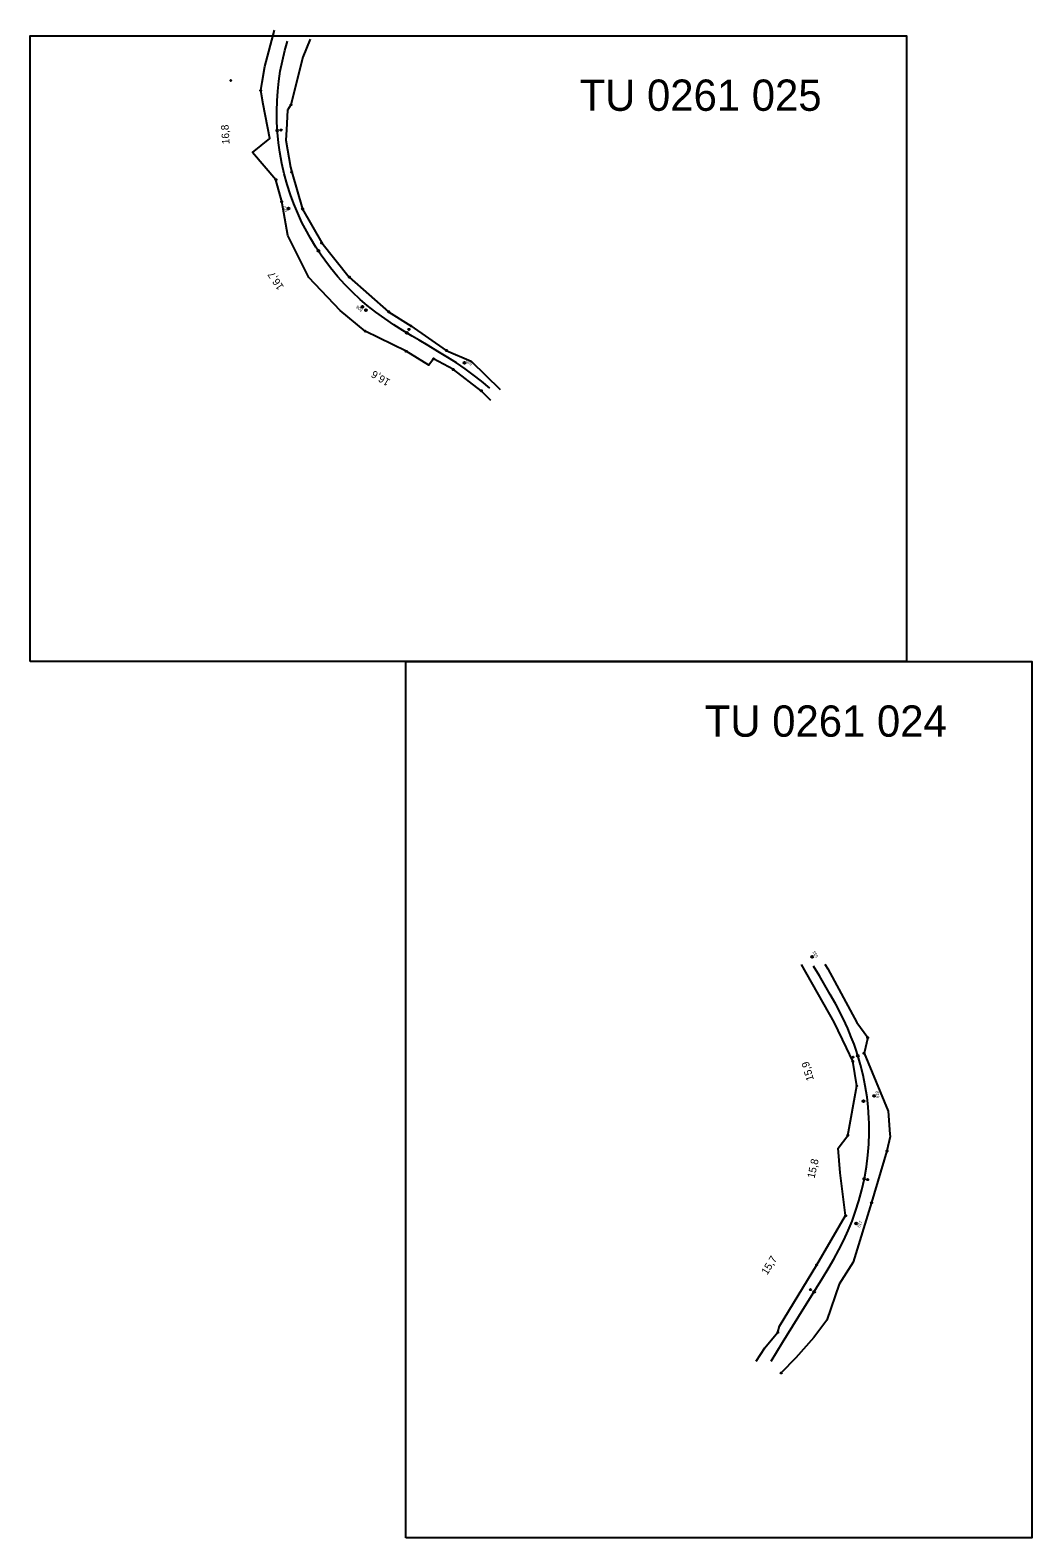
# Model space of a CAD drawing. Extents: x -849500 to -843400, y -1061500 to -1052696.
# Drawn here: x -849500 to -848700, y -1053900 to -1052696 of the extents above; entities that cross this region are included whole.
import ezdxf

# ---------------------------------------------------------------- set-up
doc = ezdxf.new("R2010")
doc.units = 0
for name, color, linetype in [('Level 1', 7, 'Continuous'), ('Level 2', 7, 'Continuous'), ('Vrstva 1', 7, 'Continuous'), ('Vrstva 53', 7, 'Continuous'), ('Vrstva 63', 7, 'Continuous'), ('Vrstva 7', 7, 'Continuous')]:
    doc.layers.add(name, color=color, linetype=linetype)

msp = doc.modelspace()

# ---------------------------------------------------------------- linework, layer by layer
at = {"layer": 'Level 1'}
for points in [[(-849500, -1053200), (-849500, -1052700), (-848800, -1052700), (-848800, -1053200), (-849500, -1053200)], [(-849200, -1053900), (-849200, -1053200), (-848700, -1053200), (-848700, -1053900), (-849200, -1053900)]]:
    msp.add_lwpolyline(points, dxfattribs=at)
at = {"layer": 'Vrstva 1'}
for points in [[(-849132.9, -1052981.5), (-849139.5, -1052975.9), (-849146.1, -1052970.8), (-849152.7, -1052966), (-849159.5, -1052961.3), (-849166.4, -1052957), (-849174.3, -1052952.2), (-849182.1, -1052947.5), (-849189.4, -1052943.3), (-849194.8, -1052940.1), (-849202.3, -1052935.5), (-849209.5, -1052930.9), (-849216.7, -1052926), (-849223.9, -1052920.9), (-849230.8, -1052915.4), (-849236.4, -1052910.6), (-849242.5, -1052904.9), (-849248.6, -1052898.7), (-849254.2, -1052892.6), (-849260.1, -1052885.4), (-849264.6, -1052879.4), (-849267.6, -1052875.3), (-849271.8, -1052869), (-849276.2, -1052861.7), (-849280.4, -1052854.1), (-849283, -1052849.1), (-849286.3, -1052841.7), (-849289.4, -1052834.2), (-849292.1, -1052827), (-849294.7, -1052818.8), (-849297.1, -1052810.3), (-849299, -1052802.1), (-849300.6, -1052792.9), (-849301.7, -1052785.5), (-849302.5, -1052777.4), (-849302.9, -1052769.1), (-849303.1, -1052760.2), (-849302.8, -1052752), (-849302.3, -1052744.2), (-849301.4, -1052736.4), (-849300.2, -1052728.2), (-849298.6, -1052720.1), (-849296.6, -1052711.7), (-849294.6, -1052704.3)], [(-848908.3, -1053758.8), (-848903.7, -1053751.4), (-848899.1, -1053743.9), (-848895.6, -1053738.3), (-848890.8, -1053730.6), (-848886, -1053722.9), (-848881.2, -1053715.3), (-848876.7, -1053708.1), (-848871.9, -1053700.3), (-848867.1, -1053692.5), (-848862.6, -1053685.1), (-848858.1, -1053677.3), (-848854.1, -1053669.9), (-848850.2, -1053662.1), (-848846.7, -1053654.5), (-848843.6, -1053647), (-848840.8, -1053639.1), (-848838.1, -1053630.9), (-848835.7, -1053622.1), (-848833.7, -1053612.9), (-848832.1, -1053603.5), (-848830.9, -1053594.3), (-848830.2, -1053585.4), (-848829.9, -1053576.6), (-848829.9, -1053569), (-848830.1, -1053564.6), (-848830.7, -1053555.8), (-848831.6, -1053547.9), (-848833, -1053539), (-848834.7, -1053530.5), (-848836.8, -1053522.2), (-848839, -1053514.7), (-848840.6, -1053509.6), (-848842, -1053505.7), (-848844.2, -1053500), (-848847, -1053493.2), (-848848.9, -1053489.2), (-848852.6, -1053481.4), (-848856.6, -1053473.7), (-848861, -1053465.9), (-848865.3, -1053458.4), (-848869.7, -1053451), (-848874.3, -1053443.3)]]:
    msp.add_lwpolyline(points, dxfattribs=at)
at = {"layer": 'Vrstva 53'}
for p, q in [((-849339.8, -1052735.8), (-849339.7, -1052735.8)), ((-849315.9, -1052743.8), (-849315.8, -1052743.8)), ((-849291.7, -1052755.2), (-849291.6, -1052755.2)), ((-849291.1, -1052809), (-849291, -1052809)), ((-849303.8, -1052815), (-849303.7, -1052815)), ((-849299.1, -1052832.5), (-849299, -1052832.5)), ((-849282.4, -1052838.5), (-849282.3, -1052838.5)), ((-849267.1, -1052865.5), (-849267, -1052865.5)), ((-849245.2, -1052892.8), (-849245.1, -1052892.8)), ((-849213.7, -1052920.5), (-849213.6, -1052920.5)), ((-849232.4, -1052936), (-849232.3, -1052936)), ((-849196, -1052931.8), (-849195.9, -1052931.8)), ((-849199.7, -1052952.1), (-849199.6, -1052952.1)), ((-849167.7, -1052951.4), (-849167.6, -1052951.4)), ((-849177.8, -1052958.2), (-849177.7, -1052958.2)), ((-849162.1, -1052966.7), (-849162, -1052966.7)), ((-849139.7, -1052983.6), (-849139.6, -1052983.6)), ((-848831.2, -1053500.4), (-848831.1, -1053500.4)), ((-848843.1, -1053519.3), (-848843, -1053519.3)), ((-848834.1, -1053512.9), (-848834, -1053512.9)), ((-848839.9, -1053538.9), (-848839.8, -1053538.9)), ((-848847, -1053578.5), (-848846.9, -1053578.5)), ((-848815.8, -1053590.9), (-848815.7, -1053590.9)), ((-848828, -1053632.2), (-848827.9, -1053632.2)), ((-848848.7, -1053642.7), (-848848.6, -1053642.7)), ((-848871.8, -1053681.9), (-848871.8, -1053681.9)), ((-848903, -1053735.8), (-848902.9, -1053735.8)), ((-848900.2, -1053768.3), (-848900.1, -1053768.3))]:
    msp.add_line(p, q, dxfattribs=at)
for points in [[(-849132.1, -1052991.4), (-849139.7, -1052983.6), (-849162, -1052966.7), (-849177.8, -1052958.2), (-849181.6, -1052963.1), (-849199.6, -1052952.1), (-849232.4, -1052936), (-849252.3, -1052919.6), (-849277.4, -1052893.2), (-849294.1, -1052859.5), (-849299.1, -1052832.5), (-849303.7, -1052815), (-849322.4, -1052793.2), (-849308.7, -1052782.2), (-849313.8, -1052754.8), (-849315.9, -1052743.8), (-849314.8, -1052737.2), (-849312.6, -1052724.6), (-849304.8, -1052695.6)], [(-849276.5, -1052702.8), (-849282.3, -1052717.1), (-849291.7, -1052755.2), (-849294.5, -1052759.4), (-849295.4, -1052775.1), (-849295.9, -1052783.5), (-849292.2, -1052804.9), (-849291, -1052809.1), (-849282.4, -1052838.6), (-849267.1, -1052865.5), (-849245.1, -1052892.8), (-849213.7, -1052920.5), (-849196, -1052931.8), (-849167.7, -1052951.4), (-849147.7, -1052960), (-849124.5, -1052982.7)], [(-848920.3, -1053758.9), (-848913.2, -1053748.1), (-848902.9, -1053735.8), (-848901.4, -1053730.8), (-848871.8, -1053681.9), (-848848.7, -1053642.6), (-848853.2, -1053608.3), (-848854.7, -1053588.7), (-848847, -1053578.5), (-848839.8, -1053538.9), (-848843, -1053519.3), (-848848.1, -1053508.6), (-848857.8, -1053488.1), (-848884, -1053441.9)], [(-848865.2, -1053441.7), (-848863, -1053445.5), (-848839.7, -1053488.2), (-848831.1, -1053500.4), (-848834, -1053512.8), (-848814.7, -1053559.2), (-848813.3, -1053577.6), (-848813.1, -1053579.5), (-848815.7, -1053590.9), (-848828, -1053632.2), (-848842.7, -1053679.8), (-848854, -1053697.4), (-848863.7, -1053726.1), (-848874.1, -1053740), (-848888.6, -1053756.1), (-848900.2, -1053768.3), (-848900.2, -1053768.3)]]:
    msp.add_lwpolyline(points, dxfattribs=at)
for centre in [(-849339.7, -1052735.8), (-849315.9, -1052743.8), (-849291.7, -1052755.2), (-849291.1, -1052809), (-849303.7, -1052815), (-849299.1, -1052832.5), (-849282.4, -1052838.5), (-849267.1, -1052865.5), (-849245.1, -1052892.8), (-849213.7, -1052920.5), (-849232.4, -1052936), (-849196, -1052931.8), (-849199.6, -1052952.1), (-849167.7, -1052951.4), (-849177.8, -1052958.2), (-849162, -1052966.7), (-849139.7, -1052983.6), (-848831.1, -1053500.4), (-848843, -1053519.3), (-848834, -1053512.9), (-848839.8, -1053538.9), (-848847, -1053578.5), (-848815.7, -1053590.9), (-848828, -1053632.2), (-848848.7, -1053642.7), (-848871.8, -1053681.9), (-848902.9, -1053735.8), (-848900.2, -1053768.3)]:
    msp.add_circle(centre, 0.499, dxfattribs=at)
at = {"layer": 'Vrstva 63'}
for p, q in [((-849293.7, -1052838), (-849293.6, -1052838)), ((-849234.8, -1052916.5), (-849234.7, -1052916.5)), ((-849232.5, -1052919.3), (-849232.1, -1052918.9)), ((-849232.4, -1052919.6), (-849231.9, -1052919.1)), ((-849232.3, -1052918.7), (-849231.8, -1052919.2)), ((-849231.8, -1052919.2), (-849232.3, -1052919.8)), ((-849231.8, -1052919.2), (-849231.2, -1052918.7)), ((-849231.2, -1052919.8), (-849231.8, -1052919.2)), ((-849231.6, -1052919.4), (-849231.1, -1052918.8)), ((-849231.4, -1052919.6), (-849231, -1052919.2)), ((-849153.1, -1052961.3), (-849153, -1052961.3)), ((-848875.4, -1053435.9), (-848875.3, -1053435.9)), ((-848835.3, -1053551.3), (-848834.9, -1053550.9)), ((-848835.2, -1053551.6), (-848834.7, -1053551.1)), ((-848835.1, -1053550.7), (-848834.5, -1053551.2)), ((-848834.5, -1053551.2), (-848835.1, -1053551.8)), ((-848834.5, -1053551.2), (-848834, -1053550.7)), ((-848834, -1053551.8), (-848834.5, -1053551.2)), ((-848834.4, -1053551.4), (-848833.9, -1053550.9)), ((-848834.2, -1053551.6), (-848833.8, -1053551.2)), ((-848826, -1053547), (-848825.9, -1053547)), ((-848840.4, -1053648.8), (-848840.3, -1053648.8))]:
    msp.add_line(p, q, dxfattribs=at)
for centre, radius in [((-849293.7, -1052838), 0.756), ((-849234.7, -1052916.5), 0.756), ((-849231.8, -1052919.2), 0.764), ((-849153.1, -1052961.3), 0.756), ((-848875.4, -1053435.9), 0.756), ((-848834.5, -1053551.2), 0.764), ((-848825.9, -1053547), 0.756), ((-848840.3, -1053648.8), 0.756)]:
    msp.add_circle(centre, radius, dxfattribs=at)
for centre, start, end in [((-849231.8, -1052919.2), 134.6025, 224.9205), ((-849231.8, -1052919.2), 315.0532, 44.9468), ((-848834.5, -1053551.2), 134.6025, 224.9205), ((-848834.5, -1053551.2), 315.0532, 44.9468)]:
    msp.add_arc(centre, 0.765, start, end, dxfattribs=at)
at = {"layer": 'Vrstva 7'}
for p, q in [((-849299.6, -1052775.4), (-849299.6, -1052775.3)), ((-849197.4, -1052934.7), (-849197.5, -1052934.6)), ((-848842.8, -1053516), (-848842.8, -1053516.1)), ((-848831.1, -1053613.9), (-848831.1, -1053613.8)), ((-848876.9, -1053701.7), (-848876.8, -1053701.6))]:
    msp.add_line(p, q, dxfattribs=at)
for centre, radius in [((-849302.6, -1052775.6), 0.75), ((-849299.6, -1052775.4), 0.5), ((-849269.8, -1052871.9), 0.75), ((-849199.1, -1052937.4), 0.75), ((-849197.5, -1052934.6), 0.5), ((-848842.8, -1053516), 0.5), ((-848838.9, -1053514.9), 0.75), ((-848833.8, -1053613.2), 0.75), ((-848831.1, -1053613.8), 0.5), ((-848876.8, -1053701.7), 0.5), ((-848873.9, -1053703.5), 0.75)]:
    msp.add_circle(centre, radius, dxfattribs=at)

# ---------------------------------------------------------------- texts
at = {"layer": 'Level 2'}
for s, p in [('TU 0261 025', (-849061.2, -1052760)), ('TU 0261 024', (-848961.2, -1053260))]:
    msp.add_text(s, height=25, dxfattribs=at).set_placement(p)
at = {"layer": 'Vrstva 63'}
for s, rotation, p in [('507', 112.5145, (-849293.9, -1052840.1)), ('506', 139.417, (-849234.3, -1052918.9)), ('505', 145.8665, (-849146.6, -1052961.7)), ('633', 121.1707, (-848870.4, -1053435.6)), ('618', 96.478, (-848821.8, -1053548.5)), ('617', 69.9575, (-848837.3, -1053652.4))]:
    msp.add_text(s, height=2.4, rotation=rotation, dxfattribs=at).set_placement(p)
at = {"layer": 'Vrstva 7'}
for s, rotation, p in [('16,8', 93.3098, (-849340.7, -1052786.5)), ('16,7', 123.6859, (-849297.1, -1052900.6)), ('16,6', 148.6948, (-849211.9, -1052975.2)), ('15,9', 106.1631, (-848874, -1053534)), ('15,8', 77.454, (-848873.6, -1053613.2)), ('15,7', 58.1064, (-848911.4, -1053690.4))]:
    msp.add_text(s, height=6, rotation=rotation, dxfattribs=at).set_placement(p)

doc.saveas('drawing.dxf')
